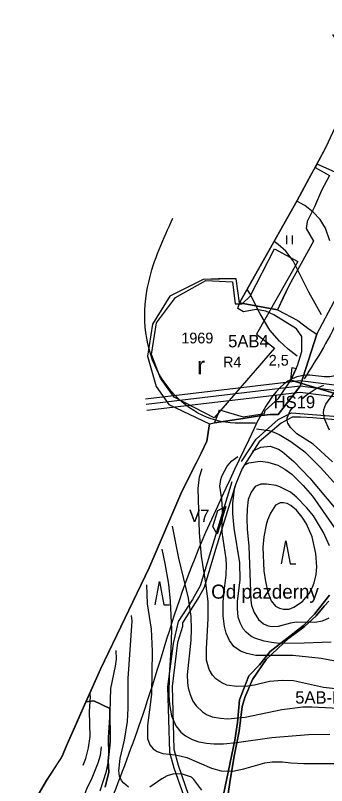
# Model space of a CAD drawing. Extents: x -684583 to -680383, y -1157874 to -1154904.
# Drawn here: x -683436 to -683060, y -1156305 to -1155373 of the extents above; entities that cross this region are included whole.
import ezdxf

# ---------------------------------------------------------------- set-up
doc = ezdxf.new("R2010")
doc.units = 0
for name, color, linetype in [('01_MÍSTNÍ_NÁZVY', 7, 'Continuous'), ('01_OBVOD PÚ', 7, 'Continuous'), ('01_PRVKY PSZ', 7, 'Continuous'), ('01_SPRÁV_HRANICE', 7, 'Continuous'), ('01_VRSTEVNICE', 7, 'Continuous'), ('02_KULTURY STAV', 7, 'Continuous'), ('03_PC_OBJEKTY_NÁVRH', 7, 'Continuous'), ('03_PC_OBJEKTY_STAV', 7, 'Continuous'), ('03_PC_STAV', 7, 'Continuous'), ('05_VHO_MELIORACE', 7, 'Continuous'), ('05_VHO_V_NÁDRŽ_STAV', 7, 'Continuous'), ('05_VHO_V_TOK', 7, 'Continuous'), ('06_BIOGEOGRAFIE', 7, 'Continuous'), ('07_ELEKTRO', 7, 'Continuous'), ('07_OCH_P A POPISY TI', 7, 'Continuous')]:
    doc.layers.add(name, color=color, linetype=linetype)

msp = doc.modelspace()

# ---------------------------------------------------------------- linework, layer by layer
at = {"layer": '01_OBVOD PÚ'}
msp.add_lwpolyline([(-683029.21, -1155463.74), (-683061.11, -1155532.25), (-683095.74, -1155596.78), (-683142.13, -1155679.03), (-683165.53, -1155720.57), (-683169.57, -1155691.76), (-683190.85, -1155691.83), (-683209.33, -1155692.36), (-683249.65, -1155712.88), (-683270.72, -1155746.6), (-683276.83, -1155785.38), (-683266.16, -1155821.93), (-683250.83, -1155843.79), (-683201.9, -1155867.06), (-683205.22, -1155888.02), (-683211.83, -1155902.78), (-683217.49, -1155913.89), (-683235.28, -1155949.16), (-683274.78, -1156041.29), (-683333.62, -1156164.09), (-683346.53, -1156193.1), (-683374.97, -1156257.7), (-683379.65, -1156268.49), (-683398.79, -1156298.66), (-683413.1, -1156322.77)], dxfattribs=at)
at = {"layer": '01_PRVKY PSZ'}
msp.add_lwpolyline([(-683103.66, -1155814.17), (-683023.93, -1155838.49), (-683005.49, -1155838.49), (-682978.82, -1155845.67), (-682966.79, -1155853.54), (-682936.74, -1155862.58), (-682930.53, -1155866.91), (-682929.33, -1155888.26), (-682839.59, -1155929.84), (-682759.46, -1156025.37)], dxfattribs=at)
at = {"layer": '01_SPRÁV_HRANICE'}
msp.add_lwpolyline([(-683029.21, -1155463.74), (-683061.11, -1155532.25), (-683095.74, -1155596.78), (-683142.13, -1155679.03), (-683165.53, -1155720.57), (-683169.57, -1155691.76), (-683190.85, -1155691.83), (-683209.33, -1155692.36), (-683249.65, -1155712.88), (-683270.72, -1155746.6), (-683276.83, -1155785.38), (-683266.16, -1155821.93), (-683250.83, -1155843.79), (-683201.9, -1155867.06), (-683205.22, -1155888.02), (-683211.83, -1155902.78), (-683217.49, -1155913.89), (-683235.28, -1155949.16), (-683274.78, -1156041.29), (-683333.62, -1156164.09), (-683346.53, -1156193.1), (-683374.97, -1156257.7), (-683379.65, -1156268.49), (-683398.79, -1156298.66), (-683413.1, -1156322.77)], dxfattribs=at)
at = {"layer": '01_VRSTEVNICE'}
for points in [[(-683072, -1155552.54), (-683045.78, -1155564.26), (-683031.95, -1155572.25), (-683022.39, -1155579.24), (-683009.98, -1155589.51), (-682997.28, -1155596.64), (-682992.15, -1155598.36), (-682985.02, -1155599.5), (-682978.03, -1155598.93), (-682970.89, -1155596.64), (-682959.2, -1155590.65), (-682946.36, -1155580.24), (-682921.25, -1155554.85), (-682906.42, -1155541.58), (-682896.01, -1155535.02), (-682884.31, -1155531.03), (-682872.9, -1155530.17), (-682861.49, -1155531.46), (-682852.21, -1155533.45), (-682843.08, -1155536.45), (-682820.69, -1155546.58), (-682807.85, -1155550), (-682800.72, -1155550.86)], [(-683056.2, -1155645.71), (-683061.47, -1155630.31), (-683068.04, -1155620.04), (-683076.59, -1155610.91), (-683086.72, -1155603.21), (-683096.2, -1155597.6)], [(-683066.32, -1155735.44), (-683081.87, -1155707.91), (-683100.56, -1155669.96), (-683109.54, -1155658.27), (-683118.67, -1155650.28), (-683123.79, -1155646.51)], [(-683095.75, -1155785.25), (-683106.7, -1155776.78), (-683117.25, -1155766.96), (-683128.94, -1155753.7), (-683140.5, -1155734.15), (-683153.19, -1155709.62), (-683156.36, -1155704.3)], [(-683090.15, -1155836.86), (-683084.87, -1155832.44), (-683072.74, -1155824.45), (-683063.61, -1155820.31)], [(-683056.77, -1155874.8), (-683062.76, -1155861.11), (-683064.04, -1155854.26), (-683063.61, -1155849.7), (-683061.33, -1155843.28), (-683048.49, -1155825.59)], [(-683053.2, -1155913.17), (-683076.45, -1155891.63), (-683096.42, -1155879.08), (-683103.98, -1155871.66), (-683107.12, -1155866.53), (-683107.97, -1155863.1), (-683107.97, -1155859.97), (-683104.27, -1155851.41), (-683100.7, -1155847.13)], [(-683145.2, -1155873.09), (-683130.23, -1155875.37), (-683124.24, -1155877.22), (-683117.53, -1155880.22), (-683103.41, -1155888.35), (-683086.44, -1155901.19), (-683067.75, -1155919.88), (-683036.22, -1155954.68)], [(-683149.88, -1155900.09), (-683139.6, -1155895.56), (-683128.52, -1155894.34), (-683118.53, -1155897.91), (-683113.97, -1155900.76), (-683099.84, -1155912.74), (-683080.59, -1155932.71), (-683049.06, -1155970.51)], [(-683035.23, -1156157.09), (-683066.89, -1156151.24), (-683101.13, -1156147.39), (-683145.63, -1156147.25), (-683156.76, -1156144.83), (-683164.18, -1156142.11), (-683172.59, -1156136.41), (-683177.73, -1156129.28), (-683181.72, -1156120.43), (-683183.72, -1156112.16), (-683185.29, -1156099.32), (-683185.29, -1156082.21), (-683183.86, -1156066.23), (-683181.58, -1156050.25), (-683181.15, -1156038.27), (-683181.72, -1156030.28), (-683186.43, -1155998.33), (-683186.14, -1155970.37), (-683187, -1155958.39), (-683189.14, -1155942.41), (-683188.14, -1155934.43), (-683187, -1155930.43), (-683180.44, -1155918.45), (-683174.73, -1155912.03), (-683167.74, -1155906.61)], [(-683158.43, -1155916.4), (-683154.48, -1155914.31), (-683140.78, -1155912.17), (-683131.37, -1155913.46), (-683119.39, -1155917.31), (-683110.83, -1155921.87), (-683102.41, -1155928.01), (-683088.43, -1155941.56), (-683077.45, -1155954.68), (-683041.5, -1156006.32)], [(-683046.07, -1156188.19), (-683064.04, -1156186.33), (-683100.27, -1156178.2), (-683113.97, -1156177.63), (-683129.37, -1156179.06), (-683147.63, -1156183.2), (-683155.33, -1156184.34), (-683169.03, -1156184.91), (-683181.01, -1156183.34), (-683187, -1156180.63), (-683193.99, -1156175.64), (-683198.27, -1156171.21), (-683202.26, -1156164.37), (-683205.26, -1156152.96), (-683205.4, -1156139.26), (-683203.26, -1156102.75), (-683203.55, -1156082.21), (-683206.26, -1156059.95), (-683211.39, -1156027.14), (-683213.96, -1155999.19), (-683215.67, -1155945.27), (-683213.82, -1155931.29), (-683210.54, -1155921.16)], [(-683054.63, -1156131.42), (-683087.43, -1156132.7), (-683117.93, -1156132.8), (-683127.09, -1156131.84), (-683135.65, -1156129.99), (-683147.06, -1156126.28), (-683151.77, -1156123.86), (-683157.47, -1156119.15), (-683161.04, -1156115.01), (-683164.75, -1156107.88), (-683167.03, -1156101.03), (-683168.17, -1156090.76), (-683167.89, -1156082.21), (-683164.89, -1156055.96), (-683165.03, -1156035.42), (-683172.02, -1155993.48), (-683173.59, -1155975.51), (-683173.73, -1155962.96), (-683171.31, -1155942.84)], [(-683056.62, -1156014.59), (-683064.04, -1155998.62), (-683076.02, -1155978.65), (-683084.15, -1155968.66), (-683096.56, -1155955.68), (-683103.98, -1155949.97), (-683116.82, -1155943.27), (-683121.38, -1155941.7), (-683132.8, -1155939.99), (-683139.64, -1155939.99), (-683146.49, -1155942.84), (-683151.62, -1155949.69), (-683154.91, -1155958.68), (-683156.33, -1155970.09), (-683156.9, -1155981.5), (-683156.33, -1155994.62), (-683154.33, -1156015.16), (-683151.77, -1156081.06), (-683150.91, -1156086.77), (-683147.92, -1156095.33), (-683142.64, -1156103.74), (-683136.65, -1156109.31), (-683130.8, -1156111.73), (-683126.23, -1156112.3), (-683118.53, -1156111.88), (-683103.41, -1156107.74), (-683097.13, -1156106.88), (-683074.6, -1156107.03), (-683065.18, -1156105.6), (-683057.05, -1156101.75)], [(-683246.91, -1155991.05), (-683239.35, -1156029.71), (-683227.51, -1156077.93), (-683224.37, -1156100.18), (-683223.95, -1156115.58), (-683224.37, -1156128.71), (-683228.79, -1156170.64), (-683228.51, -1156180.63), (-683227.65, -1156186.62), (-683225.23, -1156194.61), (-683221.95, -1156202.6), (-683218.1, -1156208.45), (-683210.39, -1156215.72), (-683205.26, -1156218.86), (-683198.41, -1156221.57), (-683188.71, -1156223.42), (-683180.15, -1156223.99), (-683158.76, -1156222.14), (-683114.54, -1156212.87), (-683088.86, -1156209.44), (-683078.31, -1156209.44), (-683037.22, -1156211.73)], [(-683259.46, -1156018.73), (-683255.61, -1156035.99), (-683251.33, -1156061.09), (-683249.19, -1156081.63), (-683247.77, -1156115.87), (-683248.62, -1156140.97), (-683250.62, -1156170.64), (-683250.9, -1156195.75), (-683250.33, -1156206.59), (-683247.62, -1156220.57), (-683242.35, -1156232.55), (-683236.5, -1156240.11), (-683230.65, -1156244.68), (-683222.66, -1156249.1), (-683214.67, -1156251.95), (-683205.26, -1156253.66), (-683196.7, -1156254.38), (-683184.72, -1156254.09), (-683169.31, -1156252.66), (-683126.52, -1156246.53), (-683082.01, -1156243.11), (-683056.34, -1156242.68)], [(-683278.01, -1156061.81), (-683277.01, -1156084.77), (-683272.3, -1156115.58), (-683271.16, -1156142.12), (-683271.87, -1156194.04), (-683276.87, -1156231.98), (-683276.58, -1156247.96), (-683273.73, -1156255.66), (-683270.02, -1156260.22), (-683265.17, -1156263.51), (-683258.32, -1156265.79), (-683242.92, -1156267.78), (-683229.22, -1156270.92), (-683199.55, -1156283.9), (-683187.57, -1156287.04), (-683173.59, -1156287.47), (-683160.47, -1156284.62), (-683134.79, -1156277.2), (-683126.23, -1156276.2), (-683113.4, -1156276.06), (-683103.41, -1156277.34), (-683087.72, -1156278.2), (-683051.49, -1156278.05)], [(-683300.12, -1156175.21), (-683295.27, -1156105.88), (-683295.98, -1156098.89)], [(-683333.92, -1156311.29), (-683326.22, -1156287.33), (-683323.94, -1156275.34), (-683323.37, -1156268.78), (-683323.94, -1156246.53), (-683321.8, -1156216), (-683321.23, -1156187.48), (-683315.38, -1156160.37), (-683314.24, -1156151.82), (-683314.52, -1156141.4)], [(-683299.69, -1156306.87), (-683305.54, -1156302.02), (-683308.1, -1156298.74), (-683310.67, -1156293.6), (-683311.24, -1156287.04), (-683309.67, -1156272.21), (-683304.4, -1156249.96), (-683301.11, -1156227.13), (-683300.26, -1156211.15), (-683300.12, -1156175.21)], [(-683354.61, -1156280.2), (-683351.18, -1156272.21), (-683347.9, -1156259.08), (-683346.05, -1156245.39), (-683346.76, -1156215.15), (-683345.76, -1156196.89), (-683346.34, -1156192.68)], [(-683332.65, -1156258.1), (-683333.77, -1156268.27), (-683336.63, -1156277.63), (-683344.05, -1156295.89), (-683350.61, -1156309.29), (-683355.32, -1156321.99), (-683356.6, -1156331.26), (-683355.75, -1156342.67), (-683352.64, -1156351.67), (-683347.9, -1156357.65), (-683343.05, -1156362.5), (-683329.98, -1156366.36), (-683320.23, -1156367.64), (-683315.09, -1156367.64), (-683301.4, -1156365.78), (-683285.85, -1156361.5)], [(-683211.25, -1156310.29), (-683220.66, -1156297.46), (-683223.66, -1156294.46), (-683235.79, -1156290.61), (-683246.05, -1156290.89), (-683252.9, -1156292.89), (-683259.61, -1156296.74), (-683273.87, -1156306.87)]]:
    msp.add_lwpolyline(points, dxfattribs=at)
msp.add_lwpolyline([(-683072.03, -1156039.98), (-683073.17, -1156024.01), (-683077.88, -1156004.04), (-683084.72, -1155988.06), (-683089.86, -1155980.07), (-683096.71, -1155971.66), (-683103.7, -1155965.95), (-683107.98, -1155963.67), (-683112.25, -1155962.53), (-683116.53, -1155962.67), (-683122.03, -1155965.56), (-683128.09, -1155975.22), (-683131.8, -1155983.78), (-683133.51, -1155989.49), (-683136.22, -1156003.75), (-683137.22, -1156016.59), (-683136.08, -1156045.12), (-683134.22, -1156057.96), (-683131.51, -1156070.79), (-683127.38, -1156081.21), (-683121.95, -1156087.62), (-683117.39, -1156090.05), (-683112.54, -1156091.48), (-683105.69, -1156091.33), (-683099.7, -1156089.05), (-683089.43, -1156082.06), (-683081.44, -1156072.51), (-683077.16, -1156064.8), (-683075.17, -1156059.67), (-683072.74, -1156049.4)], close=True, dxfattribs=at)
at = {"layer": '02_KULTURY STAV'}
for points in [[(-683006.2, -1155428.07), (-683029.21, -1155463.74), (-683061.11, -1155532.25), (-683074.32, -1155556.93), (-683056.98, -1155566.65), (-683066.36, -1155584.79), (-683075.11, -1155604.61), (-683083.75, -1155622.56), (-683084.97, -1155630.7), (-683075.94, -1155646.03), (-683105.92, -1155700.14), (-683119.61, -1155729.12), (-683095.22, -1155742), (-683081.21, -1155752.78), (-683071.96, -1155758.47), (-683036.98, -1155692.61), (-683016.49, -1155661.06), (-683001.08, -1155634.9), (-682987.04, -1155599.33), (-683014.5, -1155587.07), (-682986.93, -1155532.32), (-682971.59, -1155498.53), (-682997.53, -1155483.87), (-682979.18, -1155443.54)], [(-683074.32, -1155556.93), (-683056.98, -1155566.65), (-683066.36, -1155584.79), (-683075.11, -1155604.61), (-683083.75, -1155622.56), (-683084.97, -1155630.7), (-683075.94, -1155646.03), (-683105.92, -1155700.14), (-683111.72, -1155711.48), (-683119.61, -1155729.12), (-683165.53, -1155720.57), (-683142.13, -1155679.03), (-683095.74, -1155596.78), (-683078.81, -1155565.36)], [(-683201.9, -1155867.06), (-683195.84, -1155866.11), (-683191.37, -1155855.63), (-683189.54, -1155850.19), (-683161.02, -1155858.61), (-683135.25, -1155854.61), (-683134.54, -1155851.17), (-683118.55, -1155836.4), (-683103.66, -1155814.17), (-683095.44, -1155796.47), (-683090.22, -1155779.78), (-683090.24, -1155761.34), (-683096.53, -1155752.19), (-683123.87, -1155735.31), (-683133.59, -1155730.71), (-683145.45, -1155728.7), (-683160.89, -1155731.62), (-683167.38, -1155727.5), (-683165.53, -1155720.57), (-683169.57, -1155691.76), (-683209.33, -1155692.36), (-683249.65, -1155712.88), (-683270.72, -1155746.6), (-683276.83, -1155785.38), (-683266.16, -1155821.93), (-683250.83, -1155843.79)], [(-683195.84, -1155866.11), (-683191.37, -1155855.63), (-683189.54, -1155850.19), (-683161.02, -1155858.61), (-683135.25, -1155854.61), (-683134.54, -1155851.17), (-683118.55, -1155836.4), (-683103.66, -1155814.17), (-683095.44, -1155796.47), (-683090.22, -1155779.78), (-683090.24, -1155761.34), (-683096.53, -1155752.19), (-683123.87, -1155735.31), (-683133.59, -1155730.71), (-683145.45, -1155728.7), (-683160.89, -1155731.62), (-683167.38, -1155727.5), (-683165.53, -1155720.57), (-683119.61, -1155729.12), (-683095.22, -1155742), (-683081.21, -1155752.78), (-683071.96, -1155758.47), (-683092.14, -1155821.7), (-683118.92, -1155855.83), (-683128.5, -1155855.96), (-683138.84, -1155857.1), (-683161.14, -1155860.67)]]:
    msp.add_lwpolyline(points, close=True, dxfattribs=at)
for points in [[(-683108.82, -1155639.46), (-683108.82, -1155649.96)], [(-683101.82, -1155639.46), (-683101.82, -1155649.96)], [(-683071.96, -1155758.47), (-683036.98, -1155692.61)], [(-683327.82, -1156306.53), (-683323.6, -1156288.47), (-683324.18, -1156274.78), (-683321.83, -1156251.85), (-683322.45, -1156211.58), (-683341.68, -1156202.07), (-683351.1, -1156203.48), (-683345.17, -1156190.01), (-683333.62, -1156164.09), (-683274.78, -1156041.29), (-683235.28, -1155949.16), (-683217.49, -1155913.89), (-683211.83, -1155902.78), (-683205.22, -1155888.02), (-683201.9, -1155867.06), (-683195.84, -1155866.11), (-683161.14, -1155860.67), (-683138.84, -1155857.1), (-683128.5, -1155855.96), (-683118.92, -1155855.83), (-683092.14, -1155821.7), (-683071.96, -1155758.47)], [(-683114.96, -1156036.53), (-683109.71, -1156008.53), (-683104.46, -1156036.53), (-683097.46, -1156036.53)], [(-683267.49, -1156086.05), (-683262.24, -1156058.05), (-683256.99, -1156086.05), (-683249.99, -1156086.05)], [(-683184.73, -1156315.73), (-683171.14, -1156249.94), (-683167.9, -1156228.5), (-683165.7, -1156201.06), (-683154.24, -1156172.08), (-683141.22, -1156158.52), (-683128.69, -1156142.57), (-683088.12, -1156111.1), (-683074.73, -1156097.48), (-683056.67, -1156074.55)], [(-683056.67, -1156074.55), (-683074.73, -1156097.48), (-683088.12, -1156111.1), (-683128.69, -1156142.57), (-683141.22, -1156158.52), (-683154.24, -1156172.08), (-683165.7, -1156201.06)], [(-683057.59, -1156081.49), (-683063.12, -1156087.72), (-683072.97, -1156099.41), (-683087.46, -1156112.83), (-683105.92, -1156126.33), (-683133.41, -1156152.31), (-683149.74, -1156176.58), (-683158.98, -1156198.3), (-683162.15, -1156209), (-683165.98, -1156238.9), (-683171.5, -1156267.2), (-683176.55, -1156295.75), (-683179.6, -1156317.32)], [(-683179.6, -1156317.32), (-683176.55, -1156295.75), (-683171.5, -1156267.2), (-683165.98, -1156238.9), (-683162.15, -1156209), (-683158.98, -1156198.3), (-683149.74, -1156176.58), (-683133.41, -1156152.31), (-683105.92, -1156126.33), (-683087.46, -1156112.83), (-683072.97, -1156099.41), (-683063.12, -1156087.72), (-683057.59, -1156081.49)], [(-683413.1, -1156322.77), (-683398.79, -1156298.66), (-683380.82, -1156271.13), (-683374.97, -1156257.7), (-683351.1, -1156203.48), (-683341.68, -1156202.07), (-683322.45, -1156211.58), (-683321.83, -1156251.85), (-683324.18, -1156274.78), (-683323.6, -1156288.47), (-683327.82, -1156306.53)], [(-683165.7, -1156201.06), (-683167.9, -1156228.5), (-683171.14, -1156249.94), (-683184.73, -1156315.73)]]:
    msp.add_lwpolyline(points, dxfattribs=at)
at = {"layer": '03_PC_OBJEKTY_NÁVRH'}
for points in [[(-683162.95, -1155912.75), (-683145.43, -1155885.76), (-683118.84, -1155861.84), (-683102.86, -1155853.78), (-683046.59, -1155858.08), (-683031.82, -1155872.72), (-683020.13, -1155878.5), (-682990.45, -1155881.05), (-682972.06, -1155889.38), (-682887.85, -1155960.19), (-682765.64, -1156042.16)], [(-683174.65, -1155937.35), (-683210.22, -1156053.67), (-683213.15, -1156063.25), (-683222.33, -1156079.87), (-683239.53, -1156106.26), (-683245.78, -1156132.85), (-683252.62, -1156185.25), (-683250.28, -1156264.23), (-683244.8, -1156283.2), (-683228.39, -1156329.92), (-683241.68, -1156432.76), (-683244.02, -1156480.07), (-683236.01, -1156514.67), (-683236.01, -1156553.77), (-683245.39, -1156601.08), (-683248.71, -1156657), (-683254.96, -1156720.15), (-683258.68, -1156736.37), (-683280.56, -1156777.62), (-683294.63, -1156809.69), (-683298.73, -1156825.13), (-683296.59, -1156836.67)]]:
    msp.add_lwpolyline(points, dxfattribs=at)
msp.add_lwpolyline([(-683192.71, -1156000.63), (-683197.61, -1155991.22), (-683191.6, -1155972.15), (-683182.11, -1155967)], close=True, dxfattribs=at)
at = {"layer": '03_PC_STAV'}
msp.add_lwpolyline([(-683049.43, -1155862.22), (-683077.1, -1155860.02), (-683091.86, -1155858.93), (-683101.96, -1155858.93), (-683115.19, -1155866.44), (-683141.66, -1155888.9), (-683162.31, -1155921), (-683170.06, -1155939.83), (-683194.39, -1156019.28), (-683208.23, -1156065.02), (-683214.12, -1156076.17), (-683234.49, -1156107.94), (-683234.49, -1156112.15), (-683240.31, -1156131.81), (-683246.88, -1156185.13), (-683244.72, -1156260.59), (-683239.83, -1156280.24), (-683222.66, -1156329.19)], dxfattribs=at)
at = {"layer": '05_VHO_MELIORACE'}
msp.add_lwpolyline([(-683123.07, -1155655.51), (-683094.99, -1155670.83), (-683145.18, -1155758.47), (-683123.07, -1155775.49), (-683196.22, -1155859.73), (-683244.7, -1155835.05), (-683260.86, -1155812.08), (-683271.92, -1155783.15), (-683265.97, -1155744.86), (-683243, -1155714.22), (-683206.43, -1155693.8), (-683174.1, -1155695.5), (-683170.7, -1155721.88), (-683162.19, -1155721.88), (-683152.84, -1155712.52)], close=True, dxfattribs=at)
at = {"layer": '05_VHO_V_TOK'}
msp.add_lwpolyline([(-683102.01, -1155799.05), (-683097.2, -1155800.41), (-683103.66, -1155814.17)], close=True, dxfattribs=at)
msp.add_lwpolyline([(-683023.93, -1155838.49), (-683103.66, -1155814.17)], dxfattribs=at)
at = {"layer": '06_BIOGEOGRAFIE'}
for points in [[(-682624.87, -1154935.44), (-682669.05, -1155140.04), (-682739.65, -1155253.72), (-682834.36, -1155382.91), (-682941.12, -1155661.96), (-683008.28, -1155760.14), (-683056.49, -1155810.09), (-683084.04, -1155808.37), (-683154.45, -1155886.49), (-683231.94, -1156062.19), (-683280.08, -1156211.64), (-683362.74, -1156430.39), (-683497.05, -1156731.83), (-683541.82, -1156781.78), (-683638.25, -1156792.12), (-683701.96, -1156768), (-683817.33, -1156693.94)], [(-683053.16, -1155396.05), (-683022.17, -1155456.33), (-683017, -1155582.08), (-683044.55, -1155735.38), (-683087.6, -1155812.89)], [(-683146.15, -1155866.29), (-683194.36, -1155862.84), (-683264.96, -1155802.56), (-683275.29, -1155695.76), (-683246.02, -1155618.25)]]:
    msp.add_spline(points, degree=3, dxfattribs=at)
at = {"layer": '07_ELEKTRO'}
msp.add_lwpolyline([(-682818.44, -1155857.57), (-683092.14, -1155821.7), (-683278.29, -1155843.68)], dxfattribs=at)
at = {"layer": '07_OCH_P A POPISY TI'}
for p, q in [((-683279.11, -1155836.73), (-683092.09, -1155814.65)), ((-683092.09, -1155814.65), (-682820.07, -1155850.3)), ((-683277.47, -1155850.63), (-683092.19, -1155828.75)), ((-683092.19, -1155828.75), (-682826.85, -1155863.53))]:
    msp.add_line(p, q, dxfattribs=at)

# ---------------------------------------------------------------- texts
at = {"layer": '01_MÍSTNÍ_NÁZVY'}
msp.add_text('Od pazderny', height=17, dxfattribs=at).set_placement((-683199.78, -1156078.66))
at = {"layer": '02_KULTURY STAV'}
msp.add_text('r', height=21, dxfattribs=at).set_placement((-683216.66, -1155807.1))
at = {"layer": '03_PC_OBJEKTY_NÁVRH'}
msp.add_text('V7', height=15, dxfattribs=at).set_placement((-683226.49, -1155985.96))
at = {"layer": '03_PC_OBJEKTY_STAV'}
msp.add_text('HS19', height=15, dxfattribs=at).set_placement((-683124.31, -1155848.27))
at = {"layer": '05_VHO_MELIORACE'}
msp.add_text('1969', height=13, dxfattribs=at).set_placement((-683235.89, -1155769.84))
at = {"layer": '05_VHO_V_NÁDRŽ_STAV'}
msp.add_text('R4', height=13, dxfattribs=at).set_placement((-683185.46, -1155798.93))
at = {"layer": '05_VHO_V_TOK'}
msp.add_text('2,5', height=13, dxfattribs=at).set_placement((-683130.22, -1155796.74))
at = {"layer": '06_BIOGEOGRAFIE'}
for s, p in [('5AB4', (-683179.28, -1155774.63)), ('5AB-B3', (-683098.22, -1156205.66))]:
    msp.add_text(s, height=15, dxfattribs=at).set_placement(p)

doc.saveas('drawing.dxf')
